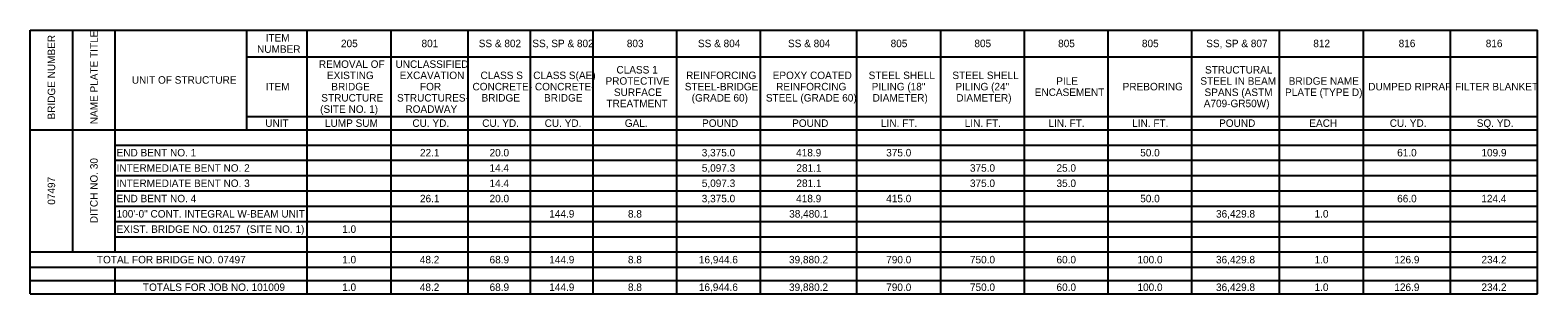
# Model space of a CAD drawing. Extents: x 192.8 to 249.4, y 129.2 to 148.9.
# Drawn here: x 224.27 to 249.4, y 139.75 to 144.15 of the extents above; entities that cross this region are included whole.
import ezdxf

# ---------------------------------------------------------------- set-up
doc = ezdxf.new("R2010")
doc.units = 0
doc.layers.add('B_Dimensions', color=7, linetype='Continuous')
doc.layers.add('B_Text', color=7, linetype='Continuous')

msp = doc.modelspace()

# ---------------------------------------------------------------- linework, layer by layer
at = {"layer": 'B_Dimensions'}
msp.add_line((224.27, 144.151), (224.27, 144.151), dxfattribs=at)
at = {"layer": 'B_Text'}
for p, q in [((224.27, 144.151), (249.399, 144.151)), ((224.27, 139.753), (224.27, 144.151)), ((224.979, 140.451), (224.979, 144.151)), ((225.688, 140.451), (225.688, 144.151)), ((227.882, 142.489), (227.882, 144.151)), ((228.89, 139.753), (228.89, 144.151)), ((230.287, 139.753), (230.287, 144.151)), ((231.572, 139.753), (231.572, 144.151)), ((232.613, 139.753), (232.613, 144.151)), ((233.655, 139.753), (233.655, 144.151)), ((235.051, 139.753), (235.051, 144.151)), ((236.447, 139.753), (236.447, 144.151)), ((238.054, 139.753), (238.054, 144.151)), ((239.45, 139.753), (239.45, 144.151)), ((240.846, 139.753), (240.846, 144.151)), ((242.242, 139.753), (242.242, 144.151)), ((243.638, 139.753), (243.638, 144.151)), ((245.1, 139.753), (245.1, 144.151)), ((246.496, 139.753), (246.496, 144.151)), ((247.948, 139.753), (247.948, 144.151)), ((249.399, 139.753), (249.399, 144.151)), ((227.882, 143.708), (249.399, 143.708)), ((227.882, 142.711), (249.399, 142.711)), ((224.27, 142.489), (249.399, 142.489)), ((225.688, 142.234), (249.399, 142.234)), ((225.688, 141.98), (249.399, 141.98)), ((225.688, 141.725), (249.399, 141.725)), ((225.688, 141.47), (249.399, 141.47)), ((225.688, 141.215), (249.399, 141.215)), ((225.688, 140.96), (249.399, 140.96)), ((225.688, 140.705), (249.399, 140.705)), ((224.27, 140.451), (249.399, 140.451)), ((224.27, 140.196), (249.399, 140.196)), ((225.688, 139.753), (225.688, 140.196)), ((224.27, 139.974), (249.399, 139.974)), ((224.27, 139.753), (249.399, 139.753))]:
    msp.add_line(p, q, dxfattribs=at)

# ---------------------------------------------------------------- texts
for s, p in [('BRIDGE NUMBER', (224.687, 142.66)), ('NAME PLATE TITLE', (225.396, 142.582)), ('DITCH NO. 30', (225.396, 140.931)), ('07497', (224.687, 141.239))]:
    msp.add_text(s, height=0.125, rotation=90, dxfattribs=at).set_placement(p)
for s, p in [('ITEM', (228.196, 143.961)), ('NUMBER', (228.053, 143.773)), ('205', (229.452, 143.867)), ('801', (230.795, 143.867)), ('SS & 802', (231.748, 143.867)), ('SS, SP & 802', (232.642, 143.867)), ('803', (234.217, 143.867)), ('SS & 804', (235.403, 143.867)), ('SS & 804', (236.904, 143.867)), ('805', (238.615, 143.867)), ('805', (240.011, 143.867)), ('805', (241.407, 143.867)), ('805', (242.804, 143.867)), ('SS, SP & 807', (243.876, 143.867)), ('812', (245.661, 143.867)), ('816', (247.084, 143.867)), ('816', (248.536, 143.867)), ('REMOVAL OF', (229.083, 143.522)), ('UNCLASSIFIED', (230.361, 143.522)), ('CLASS 1', (234.044, 143.428)), ('STRUCTURAL', (243.856, 143.428)), ('UNIT OF STRUCTURE', (225.965, 143.258)), ('ITEM', (228.196, 143.147)), ('EXISTING', (229.218, 143.335)), ('BRIDGE', (229.291, 143.147)), ('EXCAVATION', (230.431, 143.335)), ('FOR', (230.769, 143.147)), ('CONCRETE-', (231.644, 143.147)), ('CLASS S', (231.778, 143.335)), ('CLASS S(AE)', (232.657, 143.335)), ('CONCRETE-', (232.685, 143.147)), ('PROTECTIVE', (233.862, 143.241)), ('STEEL-BRIDGE', (235.183, 143.147)), ('REINFORCING', (235.205, 143.335)), ('EPOXY COATED', (236.649, 143.335)), ('REINFORCING', (236.706, 143.147)), ('STEEL SHELL', (238.248, 143.335)), ('PILING (18"', (238.299, 143.147)), ('STEEL SHELL', (239.644, 143.335)), ('PILING (24"', (239.695, 143.147)), ('PILE', (241.376, 143.241)), ('PREBORING', (242.483, 143.147)), ('STEEL IN BEAM', (243.778, 143.241)), ('BRIDGE NAME', (245.251, 143.241)), ('DUMPED RIPRAP', (246.577, 143.147)), ('FILTER BLANKET', (248.024, 143.147)), ('STRUCTURE', (229.124, 142.96)), ('STRUCTURES-', (230.386, 142.96)), ('BRIDGE', (231.795, 142.96)), ('BRIDGE', (232.837, 142.96)), ('SURFACE', (234.002, 143.053)), ('(GRADE 60)', (235.298, 142.96)), ('STEEL (GRADE 60)', (236.535, 142.96)), ('DIAMETER)', (238.315, 142.96)), ('DIAMETER)', (239.711, 142.96)), ('ENCASEMENT', (241.017, 143.053)), ('SPANS (ASTM', (243.848, 143.053)), ('PLATE (TYPE D)', (245.19, 143.053)), ('(SITE NO. 1)', (229.104, 142.772)), ('ROADWAY', (230.526, 142.772)), ('TREATMENT', (233.877, 142.866)), ('A709-GR50W)', (243.835, 142.866)), ('UNIT', (228.19, 142.538)), ('LUMP SUM', (229.185, 142.538)), ('CU. YD.', (230.642, 142.538)), ('CU. YD.', (231.806, 142.538)), ('CU. YD.', (232.847, 142.538)), ('GAL.', (234.183, 142.538)), ('POUND', (235.471, 142.538)), ('POUND', (236.973, 142.538)), ('LIN. FT.', (238.454, 142.538)), ('LIN. FT.', (239.85, 142.538)), ('LIN. FT.', (241.246, 142.538)), ('LIN. FT.', (242.642, 142.538)), ('POUND', (244.091, 142.538)), ('EACH', (245.595, 142.538)), ('CU. YD.', (246.935, 142.538)), ('SQ. YD.', (248.386, 142.538)), ('END BENT NO. 1', (225.711, 142.045)), ('22.1', (230.769, 142.045)), ('20.0', (231.929, 142.045)), ('3,375.0', (235.466, 142.045)), ('418.9', (237.04, 142.045)), ('375.0', (238.541, 142.045)), ('50.0', (242.776, 142.045)), ('61.0', (247.059, 142.045)), ('109.9', (248.464, 142.045)), ('INTERMEDIATE BENT NO. 2', (225.711, 141.79)), ('14.4', (231.928, 141.79)), ('5,097.3', (235.467, 141.79)), ('281.1', (237.044, 141.79)), ('375.0', (239.937, 141.79)), ('25.0', (241.38, 141.79)), ('INTERMEDIATE BENT NO. 3', (225.711, 141.535)), ('14.4', (231.928, 141.535)), ('5,097.3', (235.467, 141.535)), ('281.1', (237.044, 141.535)), ('375.0', (239.937, 141.535)), ('35.0', (241.38, 141.535)), ('END BENT NO. 4', (225.711, 141.28)), ('26.1', (230.769, 141.28)), ('20.0', (231.929, 141.28)), ('3,375.0', (235.466, 141.28)), ('418.9', (237.04, 141.28)), ('415.0', (238.541, 141.28)), ('50.0', (242.776, 141.28)), ('66.0', (247.059, 141.28)), ('124.4', (248.462, 141.28)), ('100\'-0" CONT. INTEGRAL W-BEAM UNIT', (225.711, 141.025)), ('144.9', (232.924, 141.025)), ('8.8', (234.236, 141.025)), ('38,480.1', (236.924, 141.025)), ('36,429.8', (244.039, 141.025)), ('1.0', (245.682, 141.025)), ('EXIST. BRIDGE NO. 01257  (SITE NO. 1)', (225.711, 140.77)), ('1.0', (229.472, 140.77)), ('TOTAL FOR BRIDGE NO. 07497', (225.383, 140.261)), ('1.0', (229.472, 140.261)), ('48.2', (230.766, 140.261)), ('68.9', (231.929, 140.261)), ('144.9', (232.924, 140.261)), ('8.8', (234.236, 140.261)), ('16,944.6', (235.418, 140.261)), ('39,880.2', (236.921, 140.261)), ('790.0', (238.541, 140.261)), ('750.0', (239.937, 140.261)), ('60.0', (241.38, 140.261)), ('100.0', (242.73, 140.261)), ('36,429.8', (244.039, 140.261)), ('1.0', (245.682, 140.261)), ('126.9', (247.012, 140.261)), ('234.2', (248.464, 140.261)), ('TOTALS FOR JOB NO. 101009', (226.15, 139.801)), ('1.0', (229.472, 139.801)), ('48.2', (230.766, 139.801)), ('68.9', (231.929, 139.801)), ('144.9', (232.924, 139.801)), ('8.8', (234.236, 139.801)), ('16,944.6', (235.418, 139.801)), ('39,880.2', (236.921, 139.801)), ('790.0', (238.541, 139.801)), ('750.0', (239.937, 139.801)), ('60.0', (241.38, 139.801)), ('100.0', (242.73, 139.801)), ('36,429.8', (244.039, 139.801)), ('1.0', (245.682, 139.801)), ('126.9', (247.012, 139.801)), ('234.2', (248.464, 139.801))]:
    msp.add_text(s, height=0.125, dxfattribs=at).set_placement(p)

doc.saveas('drawing.dxf')
